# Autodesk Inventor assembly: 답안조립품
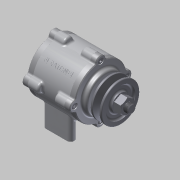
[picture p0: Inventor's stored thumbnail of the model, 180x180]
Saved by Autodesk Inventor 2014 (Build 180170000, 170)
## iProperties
Created: 2015-03
Part Number: 답안조립품
Document SubType Name: Assembly
Designer: MYHOME
Author: MYHOME
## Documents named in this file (11)
- C:\Documents and Settings\MYHOME\바탕 화면\450306v1008\답안조립품.iam
- C:\Documents and Settings\MYHOME\바탕 화면\450306v1008\본체.ipt
- C:\Documents and Settings\MYHOME\바탕 화면\450306v1008\커버2.ipt
- C:\Documents and Settings\MYHOME\바탕 화면\450306v1008\M 4 x 12.ipt
- C:\Documents and Settings\MYHOME\바탕 화면\450306v1008\커버.ipt
- C:\Documents and Settings\MYHOME\바탕 화면\450306v1008\오일실.ipt
- C:\Documents and Settings\MYHOME\바탕 화면\450306v1008\베어링 6204.ipt
- C:\Documents and Settings\MYHOME\바탕 화면\450306v1008\축.ipt
- C:\Documents and Settings\MYHOME\바탕 화면\450306v1008\키(4 x 4 x 12).ipt
- C:\Documents and Settings\MYHOME\바탕 화면\450306v1008\V벨트풀리.ipt
- C:\Documents and Settings\MYHOME\바탕 화면\450306v1008\너트 M12x1.25.ipt
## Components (14 placed, 6 different names)
1. KS B 2804 D D - 20 32 8:1
2. KS B 2023 6204 - 20 x 47 x 14:1 — 각도:1
3. KS B 2023 6204 - 20 x 47 x 14:2 — 각도:2
4. KS B 1311 (I) 4 x 4 x 12:1
5. 그루브 풀리1:1
6. KS B 1012 클래스 1 일반 - 미터 M12x1.25:1 — 각도:3
7. KS B 1003 - 미터 M 4 x 12:1
8. KS B 1003 - 미터 M 4 x 12:2
9. KS B 1003 - 미터 M 4 x 12:3
10. KS B 1003 - 미터 M 4 x 12:4
11. KS B 1003 - 미터 M 4 x 12:5
12. KS B 1003 - 미터 M 4 x 12:6
13. KS B 1003 - 미터 M 4 x 12:7
14. KS B 1003 - 미터 M 4 x 12:8
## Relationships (3: Angle 3)
- 각도:1 [Angle]: KS B 2023 6204 - 20 x 47 x 14:1
- 각도:2 [Angle]: KS B 2023 6204 - 20 x 47 x 14:2
- 각도:3 [Angle]: KS B 1012 클래스 1 일반 - 미터 M12x1.25:1
